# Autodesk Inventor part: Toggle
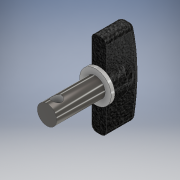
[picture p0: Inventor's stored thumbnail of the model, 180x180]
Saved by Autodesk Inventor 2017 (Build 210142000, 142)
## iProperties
Created: 2020-03
Part Number: Toggle
Material: Generic
Document SubType Name: Modeling
Designer: user
Density: 1 g/cm^3
Appearance: Default
Author: user
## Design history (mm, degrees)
sketch "Sketch1"
  geometry: C1 r 4 at (0, 0); 1 further point
  constraints: 1 centre point, 1 coincident
  dimensions: "d0" = 8 diameter of C1
extrude "Extrusion1" new body sketch "Sketch1" distance "d1" = 20; taper "d2" = 0 deg
sketch "Sketch3"
  geometry: C1 r 6.5 at (0, 0); 1 further point
  constraints: 1 centre point, 1 coincident
  dimensions: "d7" = 13 diameter of C1
extrude "Extrusion3" join sketch "Sketch3" distance "d8" = 1.5; taper "d9" = 0 deg
sketch "Sketch4"
  geometry: L1 (21.5, -6.5)-(21.5, 6.5) reference; L2 (21.5, 6.25)-(27.25, 6.25); L3 (33.5, 0)-(33.5, 0); L4 (33.5, 0)-(21.5, 0); L5 (21.5, 6.25)-(21.5, 0); A1 r 6.25 centre (27.25, 0) between (33.5, 0) and (27.25, 6.25); 1 further point
  constraints: 8 end point, 2 point on circle, 2 tangent, 1 centre point, 1 collinear, 1 horizontal, 1 midpoint, 1 perpendicular, 1 point on line
  dimensions: "d10" = 6.25 radius of A1; "d11" = 12 distance from line of L1 L3.end
revolve "Revolution1" sketch "Sketch4" stored, may be unused: angle "d12" = 90 deg
sketch "Sketch5"
  geometry: L1 (21.5, 17.5)-(21.5, -17.5); L2 (21.5, -17.5)-(33.863, -17.5); L3 (33.317, 17.5)-(21.5, 17.5); L4 (21.5, -6.5)-(21.5, 6.5) reference; L5 (0, 0)-(-2.516, 0); A1 r 81.56 centre (-46.06, -1.242) between (33.863, -17.5) and (33.317, 17.5)
  constraints: 8 end point, 2 point on circle, 1 centre point, 1 collinear, 1 horizontal, 1 perpendicular, 1 vertical, 1 other
  dimensions: "d13" = 35 distance between parallel lines of L2 L3; "d15" = 14 distance edge to line of A1 L1
extrude "Extrusion4" join sketch "Sketch5" stored distance "d16" = 6; taper "d17" = 0 deg
fillet "Fillet1" dims "d18" = 2
sketch "Sketch6"
  geometry: L1 (-4, 0)-(4, 0) reference; C1 r 2 at (0, 4); 1 further point
  constraints: 1 centre point
  dimensions: "d19" = 4 diameter of C1; "d20" = 4 distance from line of C1.centre L1
extrude "Extrusion5" cut sketch "Sketch6" stored distance "d21" = 6; taper "d22" = 0 deg
body "Solid1"
